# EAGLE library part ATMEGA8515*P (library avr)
MICROCONTROLLER 8 Kbytes FLASH 512 bytes SRAM 512 bytes EEPROM USART
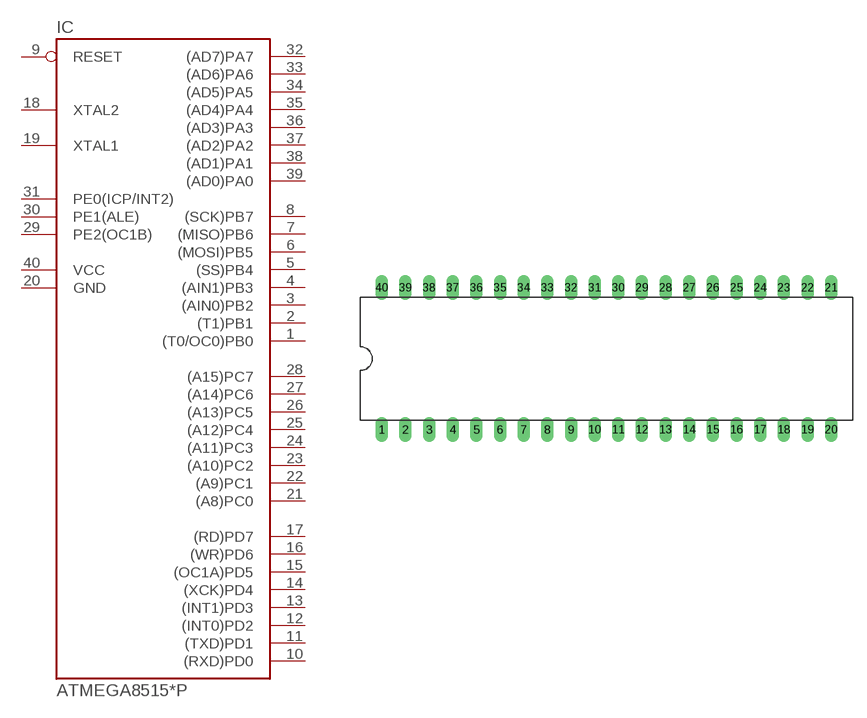
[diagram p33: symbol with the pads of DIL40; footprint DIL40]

Designator prefix IC

## ATMEGA8515-16P, ATMEGA8515L-8P  [DIL40]
1  (T0/OC0)PB0
2  (T1)PB1
3  (AIN0)PB2
4  (AIN1)PB3
5  (SS)PB4
6  (MOSI)PB5
7  (MISO)PB6
8  (SCK)PB7
9  RESET  in
10  (RXD)PD0
11  (TXD)PD1
12  (INT0)PD2
13  (INT1)PD3
14  (XCK)PD4
15  (OC1A)PD5
16  (WR)PD6
17  (RD)PD7
18  XTAL2
19  XTAL1
20  GND  pwr
21  (A8)PC0
22  (A9)PC1
23  (A10)PC2
24  (A11)PC3
25  (A12)PC4
26  (A13)PC5
27  (A14)PC6
28  (A15)PC7
29  PE2(OC1B)
30  PE1(ALE)
31  PE0(ICP/INT2)
32  (AD7)PA7
33  (AD6)PA6
34  (AD5)PA5
35  (AD4)PA4
36  (AD3)PA3
37  (AD2)PA2
38  (AD1)PA1
39  (AD0)PA0
40  VCC  pwr

## Footprint DIL40 (pad centres in mm)
Dual In Line
drill 0.813 long: 1 -24.13,-7.62; 2 -21.59,-7.62; 3 -19.05,-7.62; 4 -16.51,-7.62; 5 -13.97,-7.62; 6 -11.43,-7.62; 7 -8.89,-7.62; 8 -6.35,-7.62; 9 -3.81,-7.62; 10 -1.27,-7.62; 11 1.27,-7.62; 12 3.81,-7.62; 13 6.35,-7.62; 14 8.89,-7.62; 15 11.43,-7.62; 16 13.97,-7.62; 17 16.51,-7.62; 18 19.05,-7.62; 19 21.59,-7.62; 20 24.13,-7.62; 21 24.13,7.62; 22 21.59,7.62; 23 19.05,7.62; 24 16.51,7.62; 25 13.97,7.62; 26 11.43,7.62; 27 8.89,7.62; 28 6.35,7.62; 29 3.81,7.62; 30 1.27,7.62; 31 -1.27,7.62; 32 -3.81,7.62; 33 -6.35,7.62; 34 -8.89,7.62; 35 -11.43,7.62; 36 -13.97,7.62; 37 -16.51,7.62; 38 -19.05,7.62; 39 -21.59,7.62; 40 -24.13,7.62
